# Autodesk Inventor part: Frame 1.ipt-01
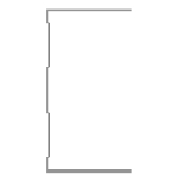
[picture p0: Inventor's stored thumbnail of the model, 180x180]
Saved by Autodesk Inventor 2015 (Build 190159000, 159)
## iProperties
Created: 2015-04
Part Number: Frame 1.ipt-01
Material: Aluminum 6061
Description: Kévin Novo
Document SubType Name: Modeling
Standard: Kevin
Designer: suporte
Standards Organization: Kevin
Language: en-US
Size Designation: (Unnamed 1)
Categories: <MemberInstance><Categories><Category DisplayName="Structural Shapes" InternalName="089c4875-fa83-4c05-b084-43b9cc11f5ed" Mnemonic="GRDR"><CategoryParameter Dis
Density: 2.7 g/cm^3
Appearance: Aluminum - Flat
_CCFamilyMember: 1
_CCFamilyDisplayName: Kévin - Kévin Novo
_FrameMemberDoc: Frame Member File
_Version: 15.0.0
_GetPNFromCC: 1
IsCustomPart: 1
Author: suporte
G_L: 1275,000 mm
G_W: 50,000 mm
G_H: 75,000 mm
+97E5C577-A316-488B-9898-4BCBE5543E85+CUTDETAIL1: Cut
+B5E3F3FC-8DAF-4209-9454-317D479D3EF3+CUTDETAIL2: Cut
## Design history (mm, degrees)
node "Start Plane"
node "End Plane"
sketch "Sketch"
  geometry: L1 (24.7, 37.5)-(24.7, 36.9); L2 (24.7, 36.9)-(-24.7, 36.9); L3 (-24.7, -36.9)-(24.7, -36.9); L4 (24.7, -36.9)-(24.7, -37.5); L5 (24.7, -37.5)-(-25.3, -37.5); L6 (-25.3, 37.5)-(24.7, 37.5); L7 (-24.7, 36.9)-(-24.7, 31.9); L8 (-24.7, 31.9)-(-23.3, 30.5); L9 (-23.3, 30.5)-(-23.3, 10.934); L10 (-23.3, 10.934)-(-24.7, 9.534); L11 (-24.7, 9.534)-(-24.7, -9.534); L12 (-24.7, -9.534)-(-23.3, -10.934); L13 (-23.3, -10.934)-(-23.3, -30.5); L14 (-23.3, -30.5)-(-24.7, -31.9); L15 (-24.7, -31.9)-(-24.7, -36.9); L16 (-25.3, -37.5)-(-25.3, -31.651); L17 (-25.3, -31.651)-(-23.9, -30.251); L18 (-23.9, -30.251)-(-23.9, -11.183); L19 (-23.9, -11.183)-(-25.3, -9.783); L20 (-25.3, -9.783)-(-25.3, 9.783); L21 (-25.3, 9.783)-(-23.9, 11.183); L22 (-23.9, 11.183)-(-23.9, 30.251); L23 (-23.9, 30.251)-(-25.3, 31.651); L24 (-25.3, 31.651)-(-25.3, 37.5); L25 (-25.3, 0)-(30.37, 0); 3 further points
  constraints: 50 end point, 10 point on line, 9 parallel, 5 perpendicular, 4 equal length, 3 midpoint, 3 vertical, 2 vertical alignment, 1 collinear, 1 horizontal, 1 horizontal alignment
  dimensions: "d3" = 0.6 distance of L1.start L1.end (= d6); "d5" = 75 distance between parallel lines of L5 L6; "d6" = 0.6 distance between parallel lines of L24 L7 (= d8); "d7" = 0.6 distance between parallel lines of L8 L23 (= d8); "d8" = 0.6 distance between parallel lines of L22 L9 (= d12); "Espessura" = 0.6 distance between parallel lines of L17 L14; "d10" = 0.6 distance between parallel lines of L13 L18 (= Espessura); "d11" = 0.6 distance between parallel lines of L12 L19 (= Espessura); "d12" = 0.6 distance between parallel lines of L21 L10 (= d11); "d13" = 5 distance of L2.end L7.end; "d15" = 135 deg angle of L9 L8; "d16" = 2 distance between parallel lines of L24 L9; "d17" = 50 distance of L6.start L1.start
extrude "Body" join sketch "Sketch" stored distance "d24" = 0.13; taper "d25" = 0 deg
node "Driven Length"
  sketch "Sketch10"
    geometry: L1 (0, 0)-(10, 0) reference
    constraints: 2 end point, 1 horizontal
  workplane "Work Plane7"
  sketch "Sketch11"
    geometry: L1 (-2, -87.5)-(12, -87.5) reference; L2 (-2, 1187.5)-(12, 1187.5) reference
    dimensions: "d27" = 1275 distance between parallel lines of L1 L2 (derived)
workplane "Work Plane8"
split "Split1"
workplane "Work Plane9"
split "Split2"
body "Solid1"
other parameters: "G_OFFSET_START" = 87.5 [user parameter; used in 1 equation term], "G_OFFSET_END" = -12.5 [user parameter; used in 1 equation term], "d22" = -87.5 (= -G_OFFSET_START), "d23" = 1187.5 (= tamanho + G_OFFSET_END), "G_L" = 1275 (= d27) [user parameter], "d34" = 90 deg
